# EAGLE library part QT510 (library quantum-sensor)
QWHEEL (tm) TOUCH SLIDER IC Source: http://www.qprox.com/downloads/manuals/e510_201.pdf
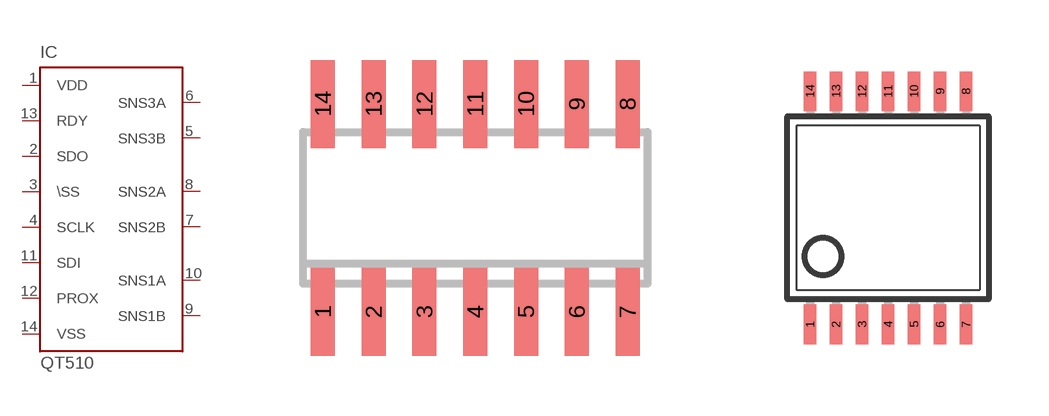
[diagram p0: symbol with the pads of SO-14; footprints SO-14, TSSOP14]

Designator prefix IC

## QT510-ISG  [SO-14]
1  VDD  pwr
2  SDO  out
3  \SS  in
4  SCLK  in
5  SNS3B  pas
6  SNS3A  pas
7  SNS2B  pas
8  SNS2A  pas
9  SNS1B  pas
10  SNS1A  pas
11  SDI  in
12  PROX  out
13  RDY  out
14  VSS  pwr

## QT510-ISSG  [TSSOP14]
Pads as for SO-14

## Footprint SO-14 (pad centres in mm)
Small Outline Narrow Plastic Gull Wing 150-mil body, package type SL
smd 0.6 x 2.2: 1 -3.81,-2.6; 2 -2.54,-2.6; 3 -1.27,-2.6; 4 0,-2.6; 5 1.27,-2.6; 6 2.54,-2.6; 7 3.81,-2.6; 8 3.81,2.6; 9 2.54,2.6; 10 1.27,2.6; 11 0,2.6; 12 -1.27,2.6; 13 -2.54,2.6; 14 -3.81,2.6

## Footprint TSSOP14 (pad centres in mm)
Thin Shrink Small Outline Plastic 14 MAX3223-MAX3243.pdf
smd 0.305 x 0.991: 1 -1.95,-2.918; 2 -1.3,-2.918; 3 -0.65,-2.918; 4 0,-2.918; 5 0.65,-2.918; 6 1.3,-2.918; 7 1.95,-2.918; 8 1.95,2.918; 9 1.3,2.918; 10 0.65,2.918; 11 0,2.918; 12 -0.65,2.918; 13 -1.3,2.918; 14 -1.95,2.918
